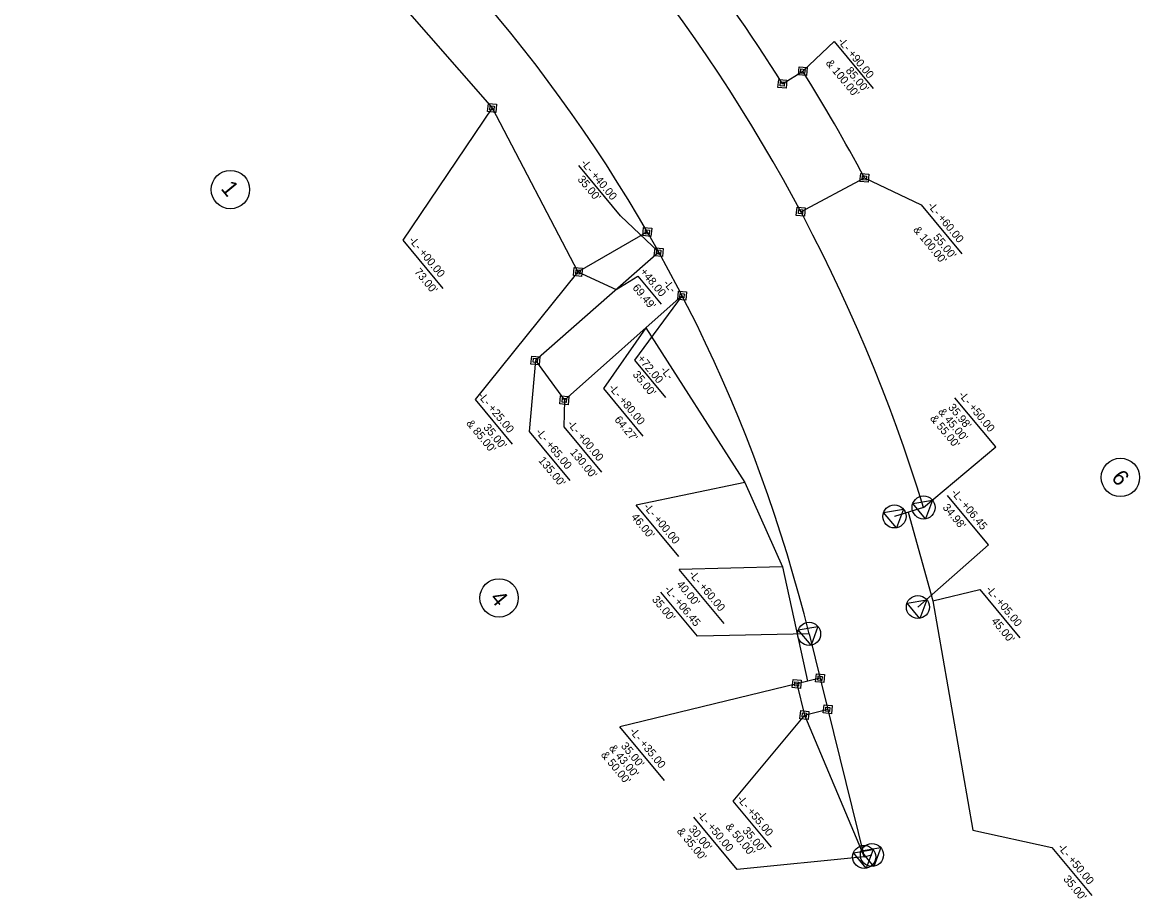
# Model space of a CAD drawing. Extents: x 2058303 to 2059235, y 688152 to 689231.
# Drawn here: x 2058537 to 2059235, y 688152 to 688700 of the extents above; entities that cross this region are included whole.
import ezdxf

# ---------------------------------------------------------------- set-up
doc = ezdxf.new("R2010")
doc.units = 0
for name, color, linetype in [('Prop Easement Aerial Utility', 7, 'Continuous'), ('Prop Easement Aerial Utility Station Offsets', 7, 'Continuous'), ('Prop Easement Construction', 7, 'Continuous'), ('Prop Easement Construction Station Offsets', 7, 'Continuous'), ('Prop Easement Permanent Drainage', 7, 'Continuous'), ('Prop Easement Permanent Drainage Station Offsets', 7, 'Continuous'), ('Prop Easement Permanent Drainage Utility', 7, 'Continuous'), ('Prop Easement Permanent Drainage Utility Station Offsets', 7, 'Continuous'), ('Prop Parcel Number CELL', 7, 'Continuous'), ('Prop Parcel Number Text', 7, 'Continuous'), ('Prop ROW Marker CELL', 7, 'Continuous'), ('Prop ROW Permanent Easement CELL', 7, 'Continuous'), ('Prop ROW RW Lines', 7, 'Continuous'), ('Prop ROW Station Offsets', 7, 'Continuous')]:
    doc.layers.add(name, color=color, linetype=linetype)

msp = doc.modelspace()

# ---------------------------------------------------------------- linework, layer by layer
at = {"layer": 'Prop Easement Aerial Utility'}
for p, q in [((2058934.55, 688556.38), (2058857.48, 688488.69)), ((2058875.59, 688463.81), (2058949.15, 688529.17)), ((2058857.48, 688488.69), (2058875.59, 688463.81))]:
    msp.add_line(p, q, dxfattribs=at)
at = {"layer": 'Prop Easement Aerial Utility Station Offsets'}
for p, q in [((2058910.67, 688579.01), (2058884.57, 688610.49)), ((2058934.55, 688556.38), (2058910.67, 688579.01)), ((2058949.15, 688529.17), (2058919.35, 688488.8)), ((2058857.48, 688488.69), (2058853.72, 688444.26)), ((2058919.35, 688488.8), (2058938.69, 688465.48)), ((2058875.59, 688463.81), (2058875.29, 688447.2)), ((2058853.72, 688444.26), (2058879.04, 688413.74)), ((2058875.29, 688447.2), (2058898.85, 688418.79))]:
    msp.add_line(p, q, dxfattribs=at)
at = {"layer": 'Prop Easement Construction'}
for p, q in [((2058884.1, 688543.98), (2058908.02, 688533.08)), ((2058926.54, 688509.08), (2058988.27, 688412.32)), ((2058988.27, 688412.32), (2059011.94, 688359.67)), ((2059090.41, 688393.85), (2059105.78, 688338.47)), ((2059011.94, 688359.67), (2059027.55, 688288.21)), ((2059105.78, 688338.47), (2059130.82, 688195.24)), ((2059025.54, 688267.11), (2059062.86, 688178.47))]:
    msp.add_line(p, q, dxfattribs=at)
at = {"layer": 'Prop Easement Construction Station Offsets'}
for p, q in [((2058908.02, 688533.08), (2058921.42, 688541.43)), ((2058921.42, 688541.43), (2058936.03, 688523.8)), ((2058926.54, 688509.08), (2058899.96, 688471.25)), ((2058899.96, 688471.25), (2058924.68, 688441.44)), ((2058988.27, 688412.32), (2058920.44, 688398.35)), ((2058947.19, 688366.08), (2058920.44, 688398.35)), ((2059011.94, 688359.67), (2058947.27, 688358.1)), ((2058975.34, 688324.25), (2058947.27, 688358.1)), ((2059105.78, 688338.47), (2059135.18, 688345.57)), ((2059135.18, 688345.57), (2059160.19, 688315.41)), ((2059130.82, 688195.24), (2059180.14, 688184.42)), ((2059180.14, 688184.42), (2059205.15, 688154.26))]:
    msp.add_line(p, q, dxfattribs=at)
at = {"layer": 'Prop Easement Permanent Drainage'}
for p, q in [((2058723.77, 688768.77), (2058830.47, 688646.47)), ((2058830.47, 688646.47), (2058884.1, 688543.98)), ((2058884.1, 688543.98), (2058927.41, 688568.97)), ((2059035.31, 688290.12), (2059020.75, 688286.53)), ((2059020.75, 688286.53), (2059025.54, 688267.11)), ((2059025.54, 688267.11), (2059040.1, 688270.7))]:
    msp.add_line(p, q, dxfattribs=at)
at = {"layer": 'Prop Easement Permanent Drainage Station Offsets'}
for p, q in [((2058830.47, 688646.47), (2058774.77, 688563.82)), ((2058774.77, 688563.82), (2058799.78, 688533.66)), ((2058884.1, 688543.98), (2058819.81, 688464.3)), ((2058819.81, 688464.3), (2058842.91, 688436.44)), ((2059020.75, 688286.53), (2058910.26, 688259.81)), ((2059025.54, 688267.11), (2058980.81, 688213.35)), ((2058938.2, 688226.12), (2058910.26, 688259.81)), ((2058980.81, 688213.35), (2059004.76, 688184.47))]:
    msp.add_line(p, q, dxfattribs=at)
at = {"layer": 'Prop Easement Permanent Drainage Utility'}
for p, q in [((2059011.8, 688661.5), (2059024.52, 688669.44)), ((2059023.26, 688581.65), (2059063, 688602.76))]:
    msp.add_line(p, q, dxfattribs=at)
for radius, start, end in [(1085, 31.98985, 44.02196), (1100, 27.97915, 31.98985)]:
    msp.add_arc((2058091.57, 688086.7), radius, start, end, dxfattribs=at)
at = {"layer": 'Prop Easement Permanent Drainage Utility Station Offsets'}
for p, q in [((2059024.52, 688669.44), (2059044.03, 688688.02)), ((2059044.03, 688688.02), (2059068.45, 688658.58)), ((2059063, 688602.76), (2059098.39, 688585.93)), ((2059098.39, 688585.93), (2059123.82, 688555.26))]:
    msp.add_line(p, q, dxfattribs=at)
at = {"layer": 'Prop Parcel Number CELL'}
for p, q in [((2058667.03, 688595.46), (2058667.03, 688595.46)), ((2059222.93, 688415.59), (2059222.93, 688415.59)), ((2058834.83, 688340.3), (2058834.83, 688340.3))]:
    msp.add_line(p, q, dxfattribs=at)
for centre in [(2058667.03, 688595.46), (2059222.93, 688415.59), (2058834.83, 688340.3)]:
    msp.add_circle(centre, 12, dxfattribs=at)
at = {"layer": 'Prop ROW Marker CELL'}
for p, q in [((2058934.55, 688556.38), (2058934.55, 688556.38)), ((2058949.15, 688529.17), (2058949.15, 688529.17)), ((2058857.48, 688488.69), (2058857.48, 688488.69)), ((2058875.59, 688463.81), (2058875.59, 688463.81)), ((2059099.97, 688396.79), (2059099.97, 688396.79)), ((2059081.79, 688391.2), (2059081.79, 688391.2)), ((2059096.41, 688334.6), (2059096.41, 688334.6)), ((2059028.48, 688317.84), (2059028.48, 688317.84)), ((2059062.86, 688178.47), (2059062.86, 688178.47)), ((2059067.71, 688179.67), (2059067.71, 688179.67))]:
    msp.add_line(p, q, dxfattribs=at)
for points in [[(2059093.21, 688399.3), (2059105.51, 688401.38), (2059101.19, 688389.68)], [(2059075.03, 688393.71), (2059087.33, 688395.79), (2059083.01, 688384.09)], [(2059089.65, 688337.11), (2059101.96, 688339.2), (2059097.63, 688327.49)], [(2059021.71, 688320.35), (2059034.02, 688322.44), (2059029.69, 688310.73)], [(2059056.1, 688180.98), (2059068.4, 688183.07), (2059064.08, 688171.36)], [(2059060.95, 688182.18), (2059073.26, 688184.26), (2059068.93, 688172.56)]]:
    msp.add_lwpolyline(points, close=True, dxfattribs=at)
for centre in [(2059099.97, 688396.79), (2059081.79, 688391.2), (2059096.41, 688334.6), (2059028.48, 688317.84), (2059062.86, 688178.47), (2059067.71, 688179.67)]:
    msp.add_circle(centre, 7.2, dxfattribs=at)
at = {"layer": 'Prop ROW Permanent Easement CELL'}
for p, q in [((2059024.52, 688669.44), (2059024.52, 688669.44)), ((2059011.8, 688661.5), (2059011.8, 688661.5)), ((2058830.47, 688646.47), (2058830.47, 688646.47)), ((2059063, 688602.76), (2059063, 688602.76)), ((2059023.26, 688581.65), (2059023.26, 688581.65)), ((2058927.41, 688568.97), (2058927.41, 688568.97)), ((2058884.1, 688543.98), (2058884.1, 688543.98)), ((2059035.31, 688290.12), (2059035.31, 688290.12)), ((2059020.75, 688286.53), (2059020.75, 688286.53)), ((2059025.54, 688267.11), (2059025.54, 688267.11)), ((2059040.1, 688270.7), (2059040.1, 688270.7))]:
    msp.add_line(p, q, dxfattribs=at)
for points in [[(2059027.29, 688671.74), (2059026.82, 688666.67), (2059021.75, 688667.15), (2059022.22, 688672.21)], [(2059025.91, 688670.59), (2059025.67, 688668.06), (2059023.14, 688668.29), (2059023.37, 688670.83)], [(2059014.57, 688663.79), (2059014.1, 688658.73), (2059009.03, 688659.2), (2059009.5, 688664.27)], [(2059013.19, 688662.65), (2059012.95, 688660.11), (2059010.42, 688660.35), (2059010.65, 688662.88)], [(2058833.24, 688648.77), (2058832.77, 688643.7), (2058827.7, 688644.17), (2058828.18, 688649.24)], [(2058831.86, 688647.62), (2058831.62, 688645.09), (2058829.09, 688645.32), (2058829.32, 688647.86)], [(2059065.77, 688605.06), (2059065.29, 688599.99), (2059060.23, 688600.47), (2059060.7, 688605.53)], [(2059064.38, 688603.91), (2059064.15, 688601.38), (2059061.61, 688601.61), (2059061.85, 688604.15)], [(2059026.03, 688583.95), (2059025.55, 688578.88), (2059020.49, 688579.35), (2059020.96, 688584.42)], [(2059024.64, 688582.8), (2059024.41, 688580.27), (2059021.87, 688580.5), (2059022.11, 688583.04)], [(2058930.18, 688571.27), (2058929.71, 688566.2), (2058924.64, 688566.67), (2058925.11, 688571.74)], [(2058928.8, 688570.12), (2058928.56, 688567.59), (2058926.03, 688567.82), (2058926.26, 688570.36)], [(2058937.32, 688558.68), (2058936.85, 688553.61), (2058931.78, 688554.08), (2058932.25, 688559.15)], [(2058935.94, 688557.53), (2058935.7, 688554.99), (2058933.17, 688555.23), (2058933.4, 688557.77)], [(2058886.87, 688546.28), (2058886.4, 688541.21), (2058881.33, 688541.69), (2058881.81, 688546.75)], [(2058885.49, 688545.13), (2058885.25, 688542.6), (2058882.72, 688542.83), (2058882.95, 688545.37)], [(2058951.92, 688531.47), (2058951.45, 688526.4), (2058946.38, 688526.87), (2058946.85, 688531.94)], [(2058950.53, 688530.32), (2058950.3, 688527.78), (2058947.76, 688528.02), (2058948, 688530.55)], [(2058860.25, 688490.99), (2058859.78, 688485.92), (2058854.71, 688486.39), (2058855.19, 688491.46)], [(2058858.87, 688489.84), (2058858.63, 688487.3), (2058856.1, 688487.54), (2058856.33, 688490.07)], [(2058878.36, 688466.1), (2058877.89, 688461.04), (2058872.82, 688461.51), (2058873.29, 688466.58)], [(2058876.97, 688464.96), (2058876.74, 688462.42), (2058874.2, 688462.66), (2058874.44, 688465.19)], [(2059023.52, 688288.83), (2059023.05, 688283.76), (2059017.98, 688284.23), (2059018.45, 688289.3)], [(2059022.14, 688287.68), (2059021.9, 688285.14), (2059019.37, 688285.38), (2059019.6, 688287.91)], [(2059038.08, 688292.42), (2059037.61, 688287.35), (2059032.54, 688287.82), (2059033.02, 688292.89)], [(2059036.7, 688291.27), (2059036.46, 688288.74), (2059033.93, 688288.97), (2059034.16, 688291.51)], [(2059042.88, 688273), (2059042.4, 688267.93), (2059037.33, 688268.41), (2059037.81, 688273.47)], [(2059028.31, 688269.41), (2059027.84, 688264.34), (2059022.77, 688264.81), (2059023.24, 688269.88)], [(2059026.93, 688268.26), (2059026.69, 688265.73), (2059024.16, 688265.96), (2059024.39, 688268.5)], [(2059041.49, 688271.85), (2059041.25, 688269.32), (2059038.72, 688269.56), (2059038.96, 688272.09)]]:
    msp.add_lwpolyline(points, close=True, dxfattribs=at)
at = {"layer": 'Prop ROW RW Lines'}
for p, q in [((2059099.97, 688396.79), (2059081.79, 688391.2)), ((2059028.48, 688317.84), (2059062.86, 688178.47)), ((2059062.86, 688178.47), (2059067.71, 688179.67))]:
    msp.add_line(p, q, dxfattribs=at)
for radius, start in [(1055, 17.09295), (965, 13.85856)]:
    msp.add_arc((2058091.57, 688086.7), radius, start, 62.50587, dxfattribs=at)
at = {"layer": 'Prop ROW Station Offsets'}
for p, q in [((2059145.06, 688434.71), (2059119.59, 688465.42)), ((2059099.97, 688396.79), (2059145.06, 688434.71)), ((2059140.54, 688373.43), (2059114.95, 688404.28)), ((2059096.41, 688334.6), (2059140.54, 688373.43)), ((2058958.69, 688316.37), (2058935.8, 688343.98)), ((2059028.48, 688317.84), (2058958.69, 688316.37)), ((2058983.5, 688170.62), (2058956.37, 688203.33)), ((2059062.86, 688178.47), (2058983.5, 688170.62))]:
    msp.add_line(p, q, dxfattribs=at)

# ---------------------------------------------------------------- texts
at = {"layer": 'Prop Easement Aerial Utility Station Offsets'}
for s, p in [('-L- +40.00', (2058885.56, 688611.94)), ("35.00'", (2058883.55, 688601.7)), ('+72.00', (2058920.86, 688489.72)), ('-L-', (2058935.3, 688482.57)), ("35.00'", (2058917.97, 688479.72)), ('-L- +00.00', (2058877.19, 688448.83)), ('-L- +65.00', (2058857.38, 688443.77)), ("135.00'", (2058859.07, 688426.06)), ("130.00'", (2058878.88, 688431.12))]:
    msp.add_text(s, height=5, rotation=309.66721, dxfattribs=at).set_placement(p)
at = {"layer": 'Prop Easement Construction Station Offsets'}
for s, p in [('+48.00', (2058922.61, 688543.91)), ("69.49'", (2058917.85, 688533.98)), ('-L-', (2058937.05, 688536.76)), ('-L- +80.00', (2058903.02, 688471.47)), ("64.27'", (2058906.59, 688451.5)), ("46.00'", (2058917.05, 688390.69)), ('-L- +00.00', (2058924.74, 688397.07)), ("40.00'", (2058945.4, 688348.6)), ('-L- +60.00', (2058953.1, 688354.98)), ('-L- +05.00', (2059138.54, 688345.44)), ("45.00'", (2059141.99, 688325.61)), ('-L- +50.00', (2059183.49, 688184.29)), ("35.00'", (2059186.94, 688164.46))]:
    msp.add_text(s, height=5, rotation=309.66721, dxfattribs=at).set_placement(p)
at = {"layer": 'Prop Easement Permanent Drainage Station Offsets'}
for s, p in [('-L- +00.00', (2058778.13, 688563.69)), ("73.00'", (2058781.58, 688543.87)), ('-L- +25.00', (2058821.26, 688466.47)), ("& 85.00'", (2058814.05, 688449.22)), ("35.00'", (2058824.71, 688446.64)), ('-L- +35.00', (2058915.96, 688256.85)), ("& 43.00'", (2058903.21, 688246.28)), ("  35.00'", (2058908.26, 688250.47)), ("& 50.00'", (2058898.17, 688242.1)), ('-L- +55.00', (2058983.1, 688214.5)), ("& 50.00'", (2058975.9, 688197.25)), ("35.00'", (2058986.55, 688194.67))]:
    msp.add_text(s, height=5, rotation=309.66721, dxfattribs=at).set_placement(p)
at = {"layer": 'Prop Easement Permanent Drainage Utility Station Offsets'}
for s, p in [('-L- +90.00', (2059046.05, 688688)), ("& 100.00'", (2059038.59, 688674.32)), ("85.00'", (2059051, 688669.62)), ('-L- +60.00', (2059102.17, 688585.29)), ("& 100.00'", (2059093.2, 688570.17)), ("55.00'", (2059105.62, 688565.47))]:
    msp.add_text(s, height=5, rotation=309.66721, dxfattribs=at).set_placement(p)
at = {"layer": 'Prop Parcel Number Text'}
for s, p in [('1', (2058660.6, 688595.93)), ('6', (2059216.8, 688415.15)), ('4', (2058828.72, 688339.83))]:
    msp.add_text(s, height=10, rotation=309.66721, dxfattribs=at).set_placement(p)
at = {"layer": 'Prop ROW Station Offsets'}
for s, p in [(" 35.98'", (2059113.82, 688460.63)), ('-L- +50.00', (2059121.52, 688467.01)), ("& 45.00'", (2059108.77, 688456.45)), ("& 55.00'", (2059103.73, 688452.26)), ('-L- +06.45', (2059116.88, 688405.88)), ("  34.98'", (2059109.18, 688399.5)), ('-L- +06.45', (2058937.73, 688345.57)), ("35.00'", (2058930.03, 688339.19)), ('-L- +50.00', (2058958.3, 688204.93)), ("& 35.00'", (2058945.55, 688194.36)), ("  30.00'", (2058950.6, 688198.55))]:
    msp.add_text(s, height=5, rotation=309.66721, dxfattribs=at).set_placement(p)

doc.saveas('drawing.dxf')
